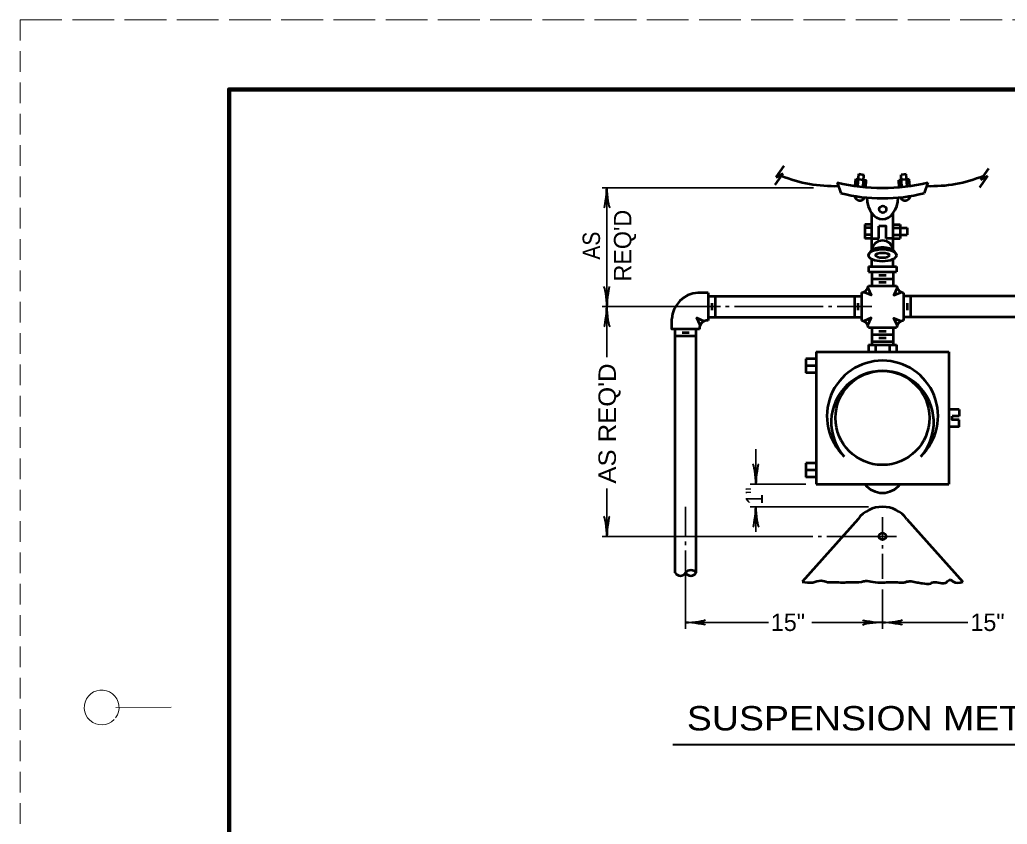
# Model space of a CAD drawing. Extents: x -1 to 679, y 1 to 441.
# Drawn here: x -1.2 to 140.6, y 325.3 to 440.8 of the extents above; entities that cross this region are included whole.
import ezdxf
from ezdxf.enums import TextEntityAlignment as Align

# ---------------------------------------------------------------- set-up
doc = ezdxf.new("R2010")
doc.units = 0
doc.linetypes.add('LONG_DASHED', pattern=[7.5, 6, -1.5])
doc.linetypes.add('MEDIUM_DASHED', pattern=[4.5, 3, -1.5])
doc.layers.add('1', color=7, linetype='Continuous', lineweight=35)
doc.layers.add('61', color=7, linetype='Continuous', lineweight=35)

msp = doc.modelspace()

# ---------------------------------------------------------------- linework, layer by layer
at = {"layer": '1', "linetype": 'MEDIUM_DASHED', "lineweight": 13}
msp.add_line((-1.178, 440.796), (-1.238, 0.756), dxfattribs=at)
at = {"layer": '1', "lineweight": 53}
for p, q in [((107.399, 418.191), (108.546, 419.83)), ((107.247, 417.092), (108.394, 418.731)), ((107.399, 418.191), (108.394, 418.731)), ((119.118, 416.913), (119.271, 418.657)), ((119.271, 418.657), (119.996, 418.515)), ((119.874, 416.77), (119.996, 418.515)), ((126.076, 418.628), (125.323, 418.513)), ((125.445, 416.767), (125.323, 418.513)), ((126.198, 416.882), (126.076, 418.628)), ((137.742, 418.357), (136.595, 416.719)), ((137.894, 419.456), (136.747, 417.818)), ((137.742, 418.357), (136.747, 417.818)), ((116.158, 417.402), (116.658, 415.902)), ((118.743, 416.922), (118.832, 417.942)), ((118.832, 417.942), (120.318, 417.741)), ((120.249, 416.754), (120.318, 417.741)), ((126.502, 417.906), (125.001, 417.739)), ((125.07, 416.754), (125.001, 417.739)), ((126.571, 416.921), (126.502, 417.906)), ((129.158, 417.402), (128.659, 415.902)), ((121.136, 407.699), (121.136, 413.009)), ((124.181, 407.699), (124.181, 413.009)), ((121.136, 411.402), (120.136, 411.402)), ((120.136, 411.402), (120.136, 409.402)), ((124.181, 411.402), (125.181, 411.402)), ((125.181, 411.402), (125.181, 409.402)), ((121.136, 410.902), (120.136, 410.902)), ((121.136, 409.902), (120.136, 409.902)), ((122.136, 409.402), (122.136, 411.152)), ((124.181, 410.902), (126.181, 410.902)), ((124.181, 409.902), (126.181, 409.902)), ((126.181, 410.902), (126.181, 409.902)), ((121.136, 409.402), (120.136, 409.402)), ((121.136, 409.402), (122.136, 409.402)), ((124.181, 409.402), (123.181, 409.402)), ((124.181, 409.402), (125.181, 409.402)), ((121.136, 405.344), (121.136, 406.402)), ((124.181, 405.344), (124.181, 406.402)), ((120.636, 405.344), (124.681, 405.344)), ((120.636, 405.344), (120.636, 404.594)), ((120.636, 404.594), (124.681, 404.594)), ((121.136, 404.594), (121.136, 402.594)), ((124.181, 404.594), (124.181, 402.594)), ((124.681, 405.344), (124.681, 404.594)), ((121.136, 403.594), (124.181, 403.594)), ((122.136, 404.094), (123.181, 404.094)), ((122.136, 403.094), (123.181, 403.094)), ((97.636, 401.594), (96.136, 401.594)), ((97.636, 401.594), (97.636, 397.594)), ((119.636, 401.601), (119.636, 397.594)), ((120.636, 402.594), (124.681, 402.594)), ((125.684, 401.6), (125.684, 397.588)), ((97.636, 401.094), (119.636, 401.094)), ((98.136, 400.094), (98.136, 399.094)), ((98.636, 401.094), (98.636, 398.094)), ((118.636, 401.094), (118.636, 398.094)), ((119.136, 400.094), (119.136, 399.094)), ((147.684, 401.094), (125.684, 401.094)), ((126.184, 400.094), (126.184, 399.094)), ((126.684, 401.094), (126.684, 398.094)), ((97.636, 398.094), (119.636, 398.094)), ((147.684, 398.094), (125.684, 398.094)), ((92.886, 361.344), (92.886, 396.344)), ((94.886, 395.844), (93.886, 395.844)), ((95.886, 361.344), (95.886, 396.344)), ((120.643, 396.594), (124.677, 396.594)), ((121.143, 396.594), (121.143, 394.094)), ((122.143, 396.094), (123.177, 396.094)), ((124.177, 396.594), (124.177, 394.094)), ((95.886, 395.344), (92.886, 395.344)), ((121.143, 395.594), (124.177, 395.594)), ((121.143, 394.594), (124.177, 394.594)), ((122.143, 395.094), (123.177, 395.094)), ((113.143, 393.094), (132.177, 393.094)), ((113.143, 393.094), (113.143, 374.094)), ((120.643, 394.094), (124.677, 394.094)), ((120.643, 394.094), (120.643, 393.094)), ((121.643, 394.094), (121.643, 393.094)), ((122.143, 394.124), (123.177, 394.124)), ((123.677, 394.094), (123.677, 393.094)), ((124.677, 394.094), (124.677, 393.094)), ((132.177, 393.094), (132.177, 374.094)), ((113.143, 392.094), (111.643, 392.094)), ((111.643, 392.094), (111.643, 390.094)), ((113.143, 391.094), (111.643, 391.094)), ((113.143, 390.094), (111.643, 390.094)), ((133.677, 384.844), (132.177, 384.844)), ((133.677, 384.844), (133.677, 383.844)), ((133.677, 383.844), (132.677, 383.844)), ((133.677, 382.344), (133.677, 383.344)), ((133.677, 382.344), (132.177, 382.344)), ((113.143, 377.094), (111.643, 377.094)), ((111.643, 377.094), (111.643, 375.094)), ((113.143, 376.094), (111.643, 376.094)), ((113.143, 375.094), (111.643, 375.094)), ((113.143, 374.094), (132.177, 374.094)), ((119.143, 369.094), (111.143, 360.094)), ((126.177, 369.094), (134.177, 360.094))]:
    msp.add_line(p, q, dxfattribs=at)
at = {"layer": '1'}
for p, q in [((112.769, 416.674), (82.386, 416.674)), ((83.073, 399.594), (83.073, 416.674)), ((99.386, 399.594), (82.386, 399.594)), ((83.073, 399.594), (83.073, 392.333)), ((100.636, 399.594), (100.136, 399.594)), ((114.136, 399.594), (101.386, 399.594)), ((115.386, 399.594), (114.886, 399.594)), ((121.136, 399.594), (116.136, 399.594)), ((104.468, 374.094), (104.468, 379.101)), ((83.073, 373.498), (83.073, 366.594)), ((111.643, 374.094), (103.66, 374.094)), ((94.386, 370.844), (94.386, 366.594)), ((120.66, 370.844), (103.66, 370.844)), ((104.468, 370.844), (104.468, 367.25)), ((122.66, 369.344), (122.66, 366.094)), ((82.386, 366.594), (112.66, 366.594)), ((113.41, 366.594), (113.91, 366.594)), ((114.66, 366.594), (124.66, 366.594)), ((94.386, 365.844), (94.386, 365.344)), ((94.386, 364.594), (94.386, 353.344)), ((122.66, 365.344), (122.66, 364.844)), ((122.66, 364.094), (122.66, 360.489)), ((122.66, 358.989), (122.66, 353.344)), ((94.386, 354.233), (106.285, 354.233))]:
    msp.add_line(p, q, dxfattribs=at)
at = {"layer": '1', "lineweight": 40}
msp.add_line((92.546, 336.708), (234.457, 336.708), dxfattribs=at)
at = {"layer": '1', "lineweight": 53}
for points in [[(123.181, 409.402), (123.181, 411.152), (122.136, 411.152)], [(120.556, 402.275), (121.041, 401.228), (119.95, 401.676)], [(124.761, 402.275), (124.276, 401.228), (125.367, 401.676)], [(96.386, 396.344), (92.386, 396.344), (92.386, 397.844)], [(96.46, 396.927), (95.975, 397.974), (97.066, 397.526)], [(120.563, 396.919), (121.047, 397.966), (119.956, 397.518)], [(124.757, 396.913), (124.272, 397.96), (125.364, 397.512)], [(133.677, 383.344), (132.677, 383.344), (132.677, 383.844)]]:
    msp.add_lwpolyline(points, dxfattribs=at)
at = {"layer": '1'}
msp.add_lwpolyline([(112.535, 354.233), (122.66, 354.233), (134.928, 354.233)], dxfattribs=at)
at = {"layer": '1', "lineweight": 53}
for centre, radius in [((122.703, 413.575), 0.5), ((122.65, 383.606), 6.75), ((122.659, 366.595), 0.5)]:
    msp.add_circle(centre, radius, dxfattribs=at)
for centre, radius, start, end in [((115.675, 436.687), 19.77, 247.65241, 271.85853), ((129.642, 436.687), 19.77, 268.14138, 292.34759), ((122.658, 445.193), 28.542, 256.83593, 283.1638), ((122.658, 439.527), 24.375, 255.74997, 284.25003), ((119.42, 415.665), 0.821, 192.33045, 332.21364), ((125.9, 415.665), 0.821, 207.78636, 347.66955), ((122.658, 407.566), 1.528, 4.98578, 175.01422), ((96.43, 397.55), 4.055, 94.15966, 175.84035), ((119.538, 402.699), 1.103, 275.11437, 291.91656), ((119.538, 402.699), 1.103, 291.91656, 354.5292), ((119.538, 402.699), 1.103, 291.91738, 337.37313), ((125.779, 402.699), 1.103, 185.4708, 248.08344), ((125.779, 402.699), 1.103, 202.62687, 248.08262), ((125.779, 402.699), 1.103, 248.08344, 265.0377), ((97.478, 396.502), 1.103, 111.91656, 188.24718), ((97.478, 396.502), 1.103, 111.91738, 157.37313), ((97.478, 396.502), 1.103, 81.75282, 111.91656), ((119.544, 396.495), 1.103, 68.08344, 85.22882), ((119.544, 396.495), 1.103, 5.16652, 68.08344), ((119.544, 396.495), 1.103, 22.62687, 68.08262), ((125.776, 396.489), 1.103, 111.91656, 174.5292), ((125.776, 396.489), 1.103, 111.91738, 157.37313), ((125.776, 396.489), 1.103, 94.77118, 111.91656), ((122.66, 383.869), 7.975, 313.60282, 226.39718), ((122.66, 382.991), 7.364, 318.31863, 221.68137), ((122.66, 376.004), 3.159, 217.18292, 322.81708), ((122.66, 366.435), 4.409, 37.09384, 142.90616), ((95.136, 360.818), 0.916, 35.00672, 144.99328), ((93.636, 361.87), 0.916, 215.00672, 324.99328), ((95.136, 361.87), 0.916, 215.00672, 324.99328)]:
    msp.add_arc(centre, radius, start, end, dxfattribs=at)
at = {"layer": '1', "lineweight": 40}
for centre, major_axis, ratio, start_param, end_param in [((82.862, 415.554), (0.176, 1.756), 0.07063, 3.1407148, 5.41811), ((83.349, 415.583), (-0.156, 1.786), 0.122415, 0.8963533, 3.1415927), ((82.797, 400.685), (0.156, -1.786), 0.122415, 0.8963533, 3.1415927), ((83.285, 400.715), (-0.176, -1.756), 0.07063, 3.1407148, 5.41811), ((82.862, 398.474), (0.176, 1.756), 0.07063, 3.1407148, 5.41811), ((82.862, 398.474), (0.176, 1.756), 0.07063, 3.1407148, 5.41811), ((83.349, 398.503), (-0.156, 1.786), 0.122415, 0.8963533, 3.1415927), ((83.349, 398.503), (-0.156, 1.786), 0.122415, 0.8963533, 3.1415927), ((104.191, 375.185), (0.156, -1.786), 0.122415, 0.8963533, 3.1415927), ((104.679, 375.215), (-0.176, -1.756), 0.07063, 3.1407148, 5.41811), ((104.256, 369.724), (0.176, 1.756), 0.07063, 3.1407148, 5.41811), ((104.744, 369.753), (-0.156, 1.786), 0.122415, 0.8963533, 3.1415927), ((82.797, 367.685), (0.156, -1.786), 0.122415, 0.8963533, 3.1415927), ((82.797, 367.685), (0.156, -1.786), 0.122415, 0.8963533, 3.1415927), ((83.285, 367.715), (-0.176, -1.756), 0.07063, 3.1407148, 5.41811), ((83.285, 367.715), (-0.176, -1.756), 0.07063, 3.1407148, 5.41811), ((95.477, 354.51), (-1.786, -0.156), 0.122415, 0.8963533, 3.1415927), ((121.54, 354.445), (1.756, -0.176), 0.07063, 3.1407148, 5.41811), ((123.751, 354.51), (-1.786, -0.156), 0.122415, 0.8963533, 3.1415927), ((95.507, 354.022), (-1.756, 0.176), 0.07063, 3.1407148, 5.41811), ((121.569, 353.957), (1.786, 0.156), 0.122415, 0.8963533, 3.1415927), ((123.781, 354.022), (-1.756, 0.176), 0.07063, 3.1407148, 5.41811)]:
    msp.add_ellipse(centre, major_axis=major_axis, ratio=ratio, start_param=start_param, end_param=end_param, dxfattribs=at)
at = {"layer": '1', "lineweight": 53}
for centre, major_axis, ratio, start_param, end_param in [((122.658, 415.402), (0, 3.25), 0.692308, 1.615522, 4.6676498), ((122.658, 406.969), (2, 0), 0.5625, 6.2831853, 9.424778)]:
    msp.add_ellipse(centre, major_axis=major_axis, ratio=ratio, start_param=start_param, end_param=end_param, dxfattribs=at)
for major_axis, ratio in [((2, 0), 0.4375), ((1, 0), 0.375)]:
    msp.add_ellipse((122.658, 406.969), major_axis=major_axis, ratio=ratio, dxfattribs=at)
msp.add_spline([(111.143, 360.094), (112.632, 359.989), (113.86, 360.246), (114.775, 360.046), (116.06, 360.017), (117.232, 359.989), (118.032, 360.046), (119.66, 360.075), (120.203, 360.217), (121.26, 360.075), (122.718, 359.989), (123.746, 360.017), (124.832, 360.017), (125.746, 359.989), (126.175, 360.103), (126.775, 360.16), (127.66, 359.989), (128.375, 359.874), (129.575, 359.846), (129.803, 359.96), (130.66, 359.96), (131.689, 359.932), (131.889, 360.046), (132.403, 360.36), (132.803, 360.103), (134.177, 360.094)], degree=3, dxfattribs=at)
at = {"layer": '61', "linetype": 'LONG_DASHED', "lineweight": 13}
msp.add_line((-1.178, 440.796), (678.842, 440.796), dxfattribs=at)
at = {"layer": '61', "lineweight": 13}
msp.add_line((12.542, 342.036), (20.522, 342.056), dxfattribs=at)
at = {"layer": '61', "lineweight": 158}
msp.add_lwpolyline([(667.862, 430.796), (28.822, 430.796), (28.822, 10.776)], dxfattribs=at)
at = {"layer": '61', "lineweight": 13}
msp.add_arc((10.52, 342.037), 2.5, 323.13009, 316.23216, dxfattribs=at)

# ---------------------------------------------------------------- texts
at = {"layer": '1'}
msp.add_text("REQ'D", height=2.5, rotation=90, dxfattribs=at).set_placement((86.593, 408.355), align=Align.CENTER)
at = {"layer": '1', "width": 0.9}
msp.add_text('AS', height=2.5, rotation=90, dxfattribs=at).set_placement((82.093, 408.355), align=Align.CENTER)
at = {"layer": '1'}
for s, width, p in [("AS REQ'D", 1.1, (84.371, 374.18)), ('1"', 0.8, (105.5, 371.197))]:
    msp.add_text(s, height=2.5, rotation=90, dxfattribs=dict(at, width=width)).set_placement(p)
for p in [(106.627, 353.01), (135.288, 353.01)]:
    msp.add_text('15"', height=2.5, dxfattribs=at).set_placement(p)
at = {"layer": '1', "width": 1.15}
msp.add_text('SUSPENSION METHOD "A" - SINGLE HANGER UNITS', height=3.5, dxfattribs=at).set_placement((94.567, 338.73))

doc.saveas('drawing.dxf')
